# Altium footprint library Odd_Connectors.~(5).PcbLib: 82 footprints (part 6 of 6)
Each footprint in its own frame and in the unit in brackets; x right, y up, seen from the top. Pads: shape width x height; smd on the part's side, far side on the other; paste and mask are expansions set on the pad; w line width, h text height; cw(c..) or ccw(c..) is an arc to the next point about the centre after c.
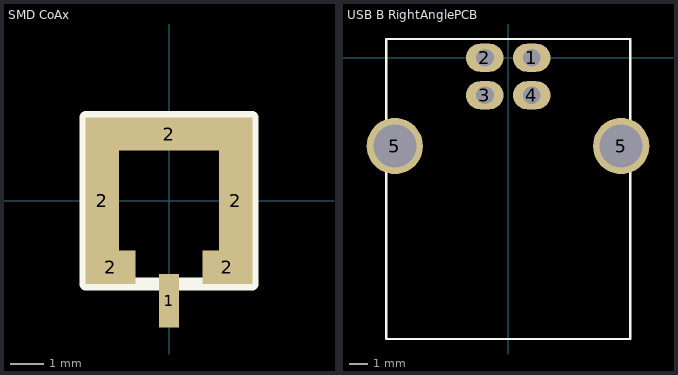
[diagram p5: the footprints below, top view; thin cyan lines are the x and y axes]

## SMD CoAx [mm] "MIL-STD-348 sm coax"
height 4.1
pads (6):
  rect 0.6x1.6 smd: 1(0,-3)
  rect 1x5 smd: 2(-2,0) 2(2,0)
  rect 1.5x1 smd: 2(-1.75,-2) 2(1.75,-2)
  rect 5x1 smd: 2(0,2)
Top Overlay:
  lines w0.381: -2.5,-2.5 2.5,-2.5 2.5,2.5 -2.5,2.5 -2.5,-2.5

## USB B RightAnglePCB [mm]
height 11.5
pads (6):
  oval 2x1.5 hole 0.95: 1(1.25,0) 2(-1.25,0) 3(-1.25,-2) 4(1.25,-2)
  round 3 hole 2.3: 5(-6.05,-4.71) 5(6.02,-4.71)
Top Overlay:
  lines w0.127: -6.5,-15 6.5,-15 6.5,1 -6.5,1 -6.5,-15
